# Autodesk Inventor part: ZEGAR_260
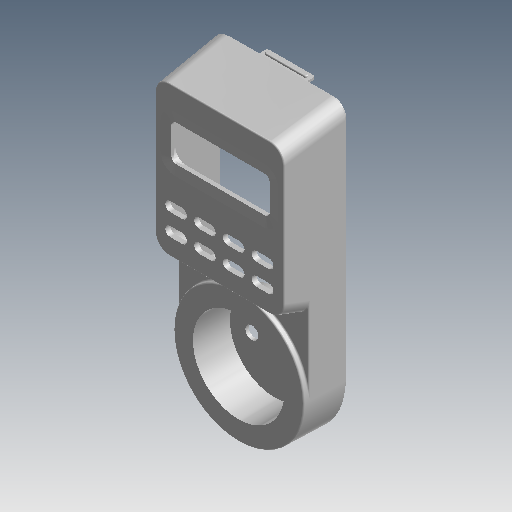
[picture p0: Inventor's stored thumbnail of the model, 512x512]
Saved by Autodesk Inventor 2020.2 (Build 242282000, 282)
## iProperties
Created: 2015-01
Part Number: ZEGAR_260
Material: Tworzywo sztuczne PC/ABS
Document SubType Name: Modeling
Designer: F.Stasiak
Density: 0.357273 g/cm^3
Appearance: Gładki - biały
Catalog Web Link: www.expertbooks.pl
Manager: www.cadconsulting.pl
Company: Fabian Stasiak CAD Consulting
Author: F.Stasiak
Subject: Zbiór ćwiczeń. Autodesk Inventor 2020. Kurs Professional
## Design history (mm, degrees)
sketch "Szkic1"
  geometry: L1 (-27.5, 0)-(-27.5, 100); L2 (-27.5, 100)-(27.5, 100); L3 (27.5, 100)-(27.5, 0); A1 r 27.5 centre (0, 0) between (-27.5, 0) and (27.5, 0); 1 further point
  constraints: 6 end point, 2 perpendicular, 2 point on circle, 1 centre point, 1 coincident, 1 tangent, 1 vertical
  dimensions: "d1" = 55 diameter of A1; "d2" = 100 distance from line of L2 point (0, 0)
extrude "Wyciągnięcie proste1" new body sketch "Szkic1" distance "d3" = 15; taper "d4" = 0 deg
sketch "Szkic2"
  geometry: L1 (27.5, 0)-(27.5, 100) reference; L2 (27.5, 100)-(-27.5, 100) reference; L3 (-27.5, 100)-(-27.5, 0) reference; L4 (-27.5, 30)-(27.5, 30); A1 r 27.5 centre (0, 0) between (-27.5, 0) and (27.5, 0) reference; 1 further point
  constraints: 2 end point, 2 point on line, 1 perpendicular
  dimensions: "d5" = 70 distance between parallel lines of L2 L4
extrude "Wyciągnięcie proste2" join sketch "Szkic2" distance "d6" = 10; taper "d7" = 0 deg
feature "Pochylenie ściany2" dims angle "d9" = 20 deg
feature "Pochylenie ściany3" dims angle "d15" = 1.5 deg
feature "Pochylenie ściany4" dims angle "d19" = 10 deg
sketch "Szkic3"
  geometry: L1 (27.107, 30)-(-27.107, 30) reference; L2 (-27.107, 30)-(-27.107, 0) reference; L3 (27.107, 0)-(27.107, 30) reference; C1 r 27.107 at (0, 0); A1 r 27.107 centre (0, 0) between (-27.107, 0) and (27.107, 0) reference; 1 further point
  constraints: 1 centre point, 1 coincident, 1 concentric
extrude "Wyciągnięcie proste3" join sketch "Szkic3" distance "d10" = 2; taper "d11" = -1.5 deg
sketch "Szkic4"
  geometry: C1 r 19 at (0, 0); 1 further point
  constraints: 1 centre point, 1 coincident
  dimensions: "d12" = 38 diameter of C1
extrude "Wyciągnięcie proste4" cut sketch "Szkic4" distance "d13" = 15; taper "d14" = -1.5 deg
fillet "Zaokrąglenie1" dims "d16" = 6
feature "Skorupa1" dims "d18" = 1.5
sketch "Szkic5"
  geometry: L1 (-9.5, 0)-(9.5, 0); C1 r 2.7 at (-9.5, 0); C2 r 2.7 at (9.5, 0); 2 further points
  constraints: 2 centre point, 2 end point, 1 coincident, 1 equal radius, 1 horizontal, 1 midpoint
  dimensions: "d20" = 5.4 diameter of C1; "d21" = 19 distance of L1.start L1.end
extrude "Wyciągnięcie proste5" cut sketch "Szkic5" extent not by distance; stored distance "d22" = 11; taper "d23" = 1.5 deg
sketch "Szkic7"
  geometry: C1 r 3 at (0, 10); 1 further point
  constraints: 1 centre point, 1 vertical alignment
  dimensions: "d232" = 6 diameter of C1; "d233" = 10 distance of point (0, 0) C1.centre
sketch "Szkic8"
  geometry: L1 (-25.999, 0)-(-25.999, 93.928) reference; L2 (25.999, 93.928)-(25.999, 0) reference; L3 (-20.068, 0)-(-25.999, 0); L4 (20.068, 0)-(25.999, 0); A1 r 20.068 centre (0, 0) between (-20.068, 0) and (20.068, 0) reference; A2 r 25.999 centre (0, 0) between (-25.999, 0) and (25.999, 0) reference; 1 further point
  constraints: 4 end point, 2 point on circle, 1 collinear, 1 perpendicular, 1 point on line
feature "Żebro1" sketch "Szkic8" dims "d31" = 0.8, "d32" = 1, "d33" = 1 deg, "d34" = 0, "d35" = 1, "d36" = 1
sketch "Szkic14"
  geometry: L1 (-26.845, 89.527)-(-26.845, 39.968) reference; L2 (-20.897, 33.64)-(20.897, 33.64) reference; L3 (26.845, 39.968)-(26.845, 89.527) reference; L4 (20.871, 95.592)-(-20.871, 95.592) reference; L5 (-20.5, 82.476)-(20.5, 82.476); L6 (20.5, 82.476)-(20.5, 67.476); L7 (20.5, 67.476)-(-20.5, 67.476); L8 (-20.5, 67.476)-(-20.5, 82.476); L9 (-20.5, 82.476)-(20.5, 67.476); L10 (20.5, 82.476)-(-20.5, 67.476); L11 (-20.5, 51.476)-(-15.5, 51.476); L12 (-20.5, 49.476)-(-15.5, 49.476); L13 (-15.5, 53.476)-(-20.5, 53.476); L14 (-3.5, 53.476)-(-8.5, 53.476); L15 (-8.5, 51.476)-(-3.5, 51.476); L16 (-8.5, 49.476)-(-3.5, 49.476); L17 (8.5, 53.476)-(3.5, 53.476); L18 (3.5, 51.476)-(8.5, 51.476); L19 (3.5, 49.476)-(8.5, 49.476); L20 (20.5, 53.476)-(15.5, 53.476); L21 (15.5, 51.476)-(20.5, 51.476); L22 (15.5, 49.476)-(20.5, 49.476); L23 (-15.5, 44.476)-(-20.5, 44.476); L24 (-20.5, 42.476)-(-15.5, 42.476); L25 (-20.5, 40.476)-(-15.5, 40.476); L26 (-3.5, 44.476)-(-8.5, 44.476); L27 (-8.5, 42.476)-(-3.5, 42.476); L28 (-8.5, 40.476)-(-3.5, 40.476); L29 (8.5, 44.476)-(3.5, 44.476); L30 (3.5, 42.476)-(8.5, 42.476); L31 (3.5, 40.476)-(8.5, 40.476); L32 (20.5, 44.476)-(15.5, 44.476); L33 (15.5, 42.476)-(20.5, 42.476); L34 (15.5, 40.476)-(20.5, 40.476); A1 r 2 centre (-20.5, 51.476) between (-20.5, 53.476) and (-20.5, 49.476); A2 r 2 centre (-15.5, 51.476) between (-15.5, 49.476) and (-15.5, 53.476); A3 r 2 centre (-3.5, 51.476) between (-3.5, 49.476) and (-3.5, 53.476); A4 r 2 centre (-8.5, 51.476) between (-8.5, 53.476) and (-8.5, 49.476); A5 r 2 centre (8.5, 51.476) between (8.5, 49.476) and (8.5, 53.476); A6 r 2 centre (3.5, 51.476) between (3.5, 53.476) and (3.5, 49.476); A7 r 2 centre (20.5, 51.476) between (20.5, 49.476) and (20.5, 53.476); A8 r 2 centre (15.5, 51.476) between (15.5, 53.476) and (15.5, 49.476); A9 r 2 centre (-15.5, 42.476) between (-15.5, 40.476) and (-15.5, 44.476); A10 r 2 centre (-20.5, 42.476) between (-20.5, 44.476) and (-20.5, 40.476); A11 r 2 centre (-3.5, 42.476) between (-3.5, 40.476) and (-3.5, 44.476); A12 r 2 centre (-8.5, 42.476) between (-8.5, 44.476) and (-8.5, 40.476); A13 r 2 centre (8.5, 42.476) between (8.5, 40.476) and (8.5, 44.476); A14 r 2 centre (3.5, 42.476) between (3.5, 44.476) and (3.5, 40.476); A15 r 2 centre (20.5, 42.476) between (20.5, 40.476) and (20.5, 44.476); A16 r 2 centre (15.5, 42.476) between (15.5, 44.476) and (15.5, 40.476); 16 further points; 4 other entities
  constraints: 76 end point, 32 point on circle, 16 centre point, 5 midpoint, 4 tangent, 3 horizontal, 3 parallel, 1 collinear, 1 perpendicular, 1 vertical, 1 vertical alignment, 87 other
  dimensions: "d89" = 41 distance of L6.end L7.end; "d90" = 15 distance of L5.end L6.end; "d91" = 5 distance of L11.start L11.end; "d92" = 4 diameter of A2; "d93" = 16 distance between parallel lines of L7 L11; "d94" = 0 distance from line of L8 L11.start; "d97" = 12 distance of L13.start L14.start; "d100" = 9 distance of L13.start L23.start; "d103" = 0 distance from line of L6 L21.end (derived)
extrude "Wyciągnięcie proste11" cut sketch "Szkic14" extent not by distance; stored distance "d104" = 4; taper "d105" = 0 deg
fillet "Zaokrąglenie4" dims "d106" = 2
sketch "Szkic15"
  geometry: L1 (5.423, 5.786)-(0.423, 5.786) reference; L2 (0.423, 9.786)-(5.423, 9.786) reference; L3 (29.423, 5.786)-(24.423, 5.786) reference; L4 (24.423, 9.786)-(29.423, 9.786) reference; L5 (5.423, 14.786)-(0.423, 14.786) reference; L6 (0.423, 18.786)-(5.423, 18.786) reference; L7 (29.423, 14.786)-(24.423, 14.786) reference; L8 (24.423, 18.786)-(29.423, 18.786) reference; L9 (36.423, 18.786)-(41.423, 18.786) reference; L10 (41.423, 14.786)-(36.423, 14.786) reference; L11 (17.423, 14.786)-(12.423, 14.786) reference; L12 (12.423, 18.786)-(17.423, 18.786) reference; L13 (41.423, 5.786)-(36.423, 5.786) reference; L14 (36.423, 9.786)-(41.423, 9.786) reference; L15 (17.423, 5.786)-(12.423, 5.786) reference; L16 (12.423, 9.786)-(17.423, 9.786) reference; L17 (41.423, 45.786)-(41.423, 34.786) reference; L18 (39.423, 32.786)-(2.423, 32.786) reference; L19 (0.423, 34.786)-(0.423, 45.786) reference; L20 (2.423, 47.786)-(39.423, 47.786) reference; L21 (0.02, 59.643)-(41.826, 59.643) reference; L22 (-4.461, 4.746)-(-4.461, 55.095) reference; L23 (41.846, 0)-(0, 0) reference; L24 (46.307, 55.095)-(46.307, 4.746) reference; L25 (0.423, 16.786)-(41.423, 16.786); L26 (0.423, 13.786)-(41.423, 13.786); L27 (41.423, 19.786)-(0.423, 19.786); L28 (0.423, 7.786)-(41.423, 7.786); L29 (0.423, 4.786)-(41.423, 4.786); L30 (41.423, 10.786)-(0.423, 10.786); A1 r 2 centre (5.423, 7.786) between (5.423, 5.786) and (5.423, 9.786) reference; A2 r 2 centre (0.423, 7.786) between (0.423, 9.786) and (0.423, 5.786) reference; A3 r 2 centre (29.423, 7.786) between (29.423, 5.786) and (29.423, 9.786) reference; A4 r 2 centre (24.423, 7.786) between (24.423, 9.786) and (24.423, 5.786) reference; A5 r 2 centre (5.423, 16.786) between (5.423, 14.786) and (5.423, 18.786) reference; A6 r 2 centre (0.423, 16.786) between (0.423, 18.786) and (0.423, 14.786) reference; A7 r 2 centre (29.423, 16.786) between (29.423, 14.786) and (29.423, 18.786) reference; A8 r 2 centre (24.423, 16.786) between (24.423, 18.786) and (24.423, 14.786) reference; A9 r 2 centre (36.423, 16.786) between (36.423, 18.786) and (36.423, 14.786) reference; A10 r 2 centre (41.423, 16.786) between (41.423, 14.786) and (41.423, 18.786) reference; A11 r 2 centre (17.423, 16.786) between (17.423, 14.786) and (17.423, 18.786) reference; A12 r 2 centre (12.423, 16.786) between (12.423, 18.786) and (12.423, 14.786) reference; A13 r 2 centre (41.423, 7.786) between (41.423, 5.786) and (41.423, 9.786) reference; A14 r 2 centre (36.423, 7.786) between (36.423, 9.786) and (36.423, 5.786) reference; A15 r 2 centre (17.423, 7.786) between (17.423, 5.786) and (17.423, 9.786) reference; A16 r 2 centre (12.423, 7.786) between (12.423, 9.786) and (12.423, 5.786) reference; A17 r 2 centre (39.423, 34.786) between (39.423, 32.786) and (41.423, 34.786) reference; A18 r 2 centre (2.423, 34.786) between (0.423, 34.786) and (2.423, 32.786) reference; A19 r 2 centre (2.423, 45.786) between (2.423, 47.786) and (0.423, 45.786) reference; A20 r 2 centre (39.423, 45.786) between (41.423, 45.786) and (39.423, 47.786) reference; A21 r 3 centre (0.423, 16.786) between (0.423, 19.786) and (0.423, 13.786); A22 r 3 centre (41.423, 16.786) between (41.423, 13.786) and (41.423, 19.786); A23 r 3 centre (0.423, 7.786) between (0.423, 10.786) and (0.423, 4.786); A24 r 3 centre (41.423, 7.786) between (41.423, 4.786) and (41.423, 10.786); 7 further points; 4 other entities
  constraints: 16 end point, 8 point on circle, 8 tangent, 4 centre point, 3 parallel, 2 midpoint, 1 horizontal, 4 other
  dimensions: "d107" = 6 diameter of A22; "d108" = 6 diameter of A24
extrude "Wyciągnięcie proste12" join sketch "Szkic15" distance "d109" = 0.5; taper "d110" = 0 deg
feature "Występ1" dims "d140" = 1.2, "d141" = 0.5, "d142" = 0, "d143" = 1.5 deg, "d144" = 0, "d145" = 0
chamfer "Faza2" distance "d146" = 4; stored, may be unused: second distance "d147" = 0.5, angle "d148" = 45 deg
fillet "Zaokrąglenie6" dims "d154" = 0.6
node "Płaszczyzna konstrukcyjna3"
sketch "Szkic23"
  geometry: L1 (10, -20)-(-10, -20); L2 (-10, -20)-(-10, -10); L3 (-10, -10)-(10, -10); L4 (10, -10)-(10, -20); L5 (21.525, -15)-(-21.525, -15) reference; 2 further points
  constraints: 8 end point, 2 equal length, 1 horizontal, 1 midpoint, 1 perpendicular, 1 vertical alignment
  dimensions: "d205" = 20 distance of L2.end L3.end; "d206" = 10 distance of L1.end L2.end; "d207" = 5 distance between parallel lines of L1 L5
extrude "Wyciągnięcie proste16" join sketch "Szkic23" distance "d208" = 1; taper "d209" = 0 deg
sketch "Szkic24"
  geometry: L1 (-8, 18)-(8, 18); L2 (-8, 17.25)-(8, 17.25); L3 (8, 18.75)-(-8, 18.75); L4 (10, 20)-(-10, 20) reference; A1 r 0.75 centre (-8, 18) between (-8, 18.75) and (-8, 17.25); A2 r 0.75 centre (8, 18) between (8, 17.25) and (8, 18.75); 7 further points
  constraints: 8 end point, 4 point on circle, 4 tangent, 3 midpoint, 2 centre point, 2 vertical alignment, 1 horizontal alignment, 1 parallel
  dimensions: "d210" = 16 distance of L1.start L1.end; "d211" = 1.5 diameter of A2; "d216" = 2 distance between parallel lines of L4 L1
extrude "Wyciągnięcie proste17" join sketch "Szkic24" distance "d212" = 0.75; taper "d213" = 0 deg
fillet "Zaokrąglenie8" dims "d214" = 0.5
fillet "Zaokrąglenie9" dims "d215" = 1
sketch "Szkic25"
  geometry: L1 (39.423, 32.786)-(2.423, 32.786) reference; L2 (0.423, 34.786)-(0.423, 45.786) reference; L3 (2.423, 47.786)-(39.423, 47.786) reference; L4 (41.423, 45.786)-(41.423, 34.786) reference; L5 (39.423, 50.786)-(2.423, 50.786); L6 (-2.577, 45.786)-(-2.577, 34.786); L7 (2.423, 29.786)-(39.423, 29.786); L8 (44.423, 34.786)-(44.423, 45.786); L9 (2.423, 50.036)-(39.423, 50.036); L10 (43.673, 45.786)-(43.673, 34.786); L11 (39.423, 30.536)-(2.423, 30.536); L12 (-1.827, 34.786)-(-1.827, 45.786); A1 r 2 centre (2.423, 34.786) between (0.423, 34.786) and (2.423, 32.786) reference; A2 r 2 centre (2.423, 45.786) between (2.423, 47.786) and (0.423, 45.786) reference; A3 r 2 centre (39.423, 45.786) between (41.423, 45.786) and (39.423, 47.786) reference; A4 r 2 centre (39.423, 34.786) between (39.423, 32.786) and (41.423, 34.786) reference; A5 r 5 centre (2.423, 45.786) between (2.423, 50.786) and (-2.577, 45.786); A6 r 5 centre (2.423, 34.786) between (-2.577, 34.786) and (2.423, 29.786); A7 r 5 centre (39.423, 34.786) between (39.423, 29.786) and (44.423, 34.786); A8 r 5 centre (39.423, 45.786) between (44.423, 45.786) and (39.423, 50.786); A9 r 4.25 centre (39.423, 45.786) between (43.673, 45.786) and (39.423, 50.036); A10 r 4.25 centre (39.423, 34.786) between (39.423, 30.536) and (43.673, 34.786); A11 r 4.25 centre (2.423, 34.786) between (-1.827, 34.786) and (2.423, 30.536); A12 r 4.25 centre (2.423, 45.786) between (2.423, 50.036) and (-1.827, 45.786); 1 further point
  constraints: 16 end point, 16 point on circle, 8 centre point, 14 other
  dimensions: "d223" = 3 distance between parallel lines of L3 L5; "d224" = 0.75 distance between parallel lines of L5 L9
extrude "Wyciągnięcie proste20" join sketch "Szkic25" distance "d225" = 3; taper "d226" = -1 deg
sketch "Szkic26"
  geometry: L1 (38.185, -5.05)-(4.185, -5.05); C1 r 2.526 at (38.185, -5.05); C2 r 2.526 at (4.185, -5.05); A1 r 25.646 centre (21.185, -31.05) between (46.823, -30.423) and (-4.454, -30.423) reference; 3 further points
  constraints: 2 centre point, 2 end point, 1 equal radius, 1 horizontal, 1 midpoint, 1 point on circle, 1 vertical alignment
  dimensions: "d227" = 34 distance of L1.end L1.start; "d228" = 26 distance from line of A1.centre L1
extrude "Wyciągnięcie proste21" join sketch "Szkic26" distance "d229" = 8; taper "d230" = -1 deg
extrude "Wyciągnięcie proste22" join sketch "Szkic7" distance "d234" = 6; taper "d235" = -1 deg
sketch "Szkic27"
  geometry: C1 r 3 at (0, 10) reference; C2 r 2.4 at (0, 10); 1 further point
  constraints: 1 centre point, 1 coincident
  dimensions: "d236" = 4.8 diameter of C2
extrude "Wyciągnięcie proste23" cut sketch "Szkic27" extent not by distance; stored distance "d237" = 6; taper "d238" = -1 deg
node "Bryła1"
node "Pętla rzutowana1"
node "Pętla rzutowana2"
node "Pętla rzutowana7"
node "Pętla rzutowana8"
other parameters: "d204" = 97.6
